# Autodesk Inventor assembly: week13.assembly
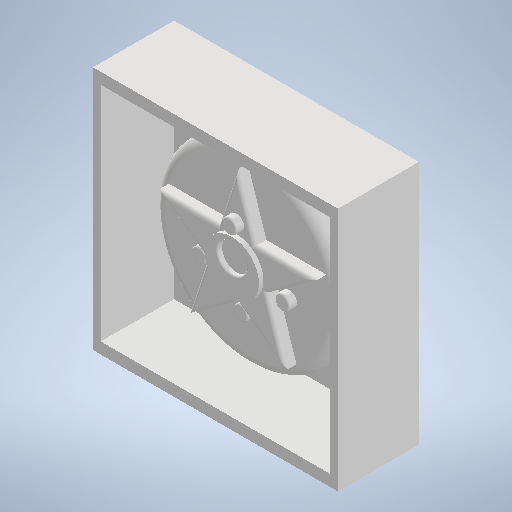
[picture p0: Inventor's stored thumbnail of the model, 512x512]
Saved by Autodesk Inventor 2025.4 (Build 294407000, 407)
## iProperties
Created: 2026-04
Part Number: week13.assembly
Document SubType Name: Assembly
Designer: FLB013
Author: FLB013
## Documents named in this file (3)
- C:\Users\flb013\Desktop\week13.assembly.iam
- C:\Users\flb013\Desktop\week13.caja.ipt
- C:\Users\flb013\Desktop\week13.sailormoon.ipt
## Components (2 placed, 2 different names)
1. week13.caja:1
2. week13.sailormoon:1
